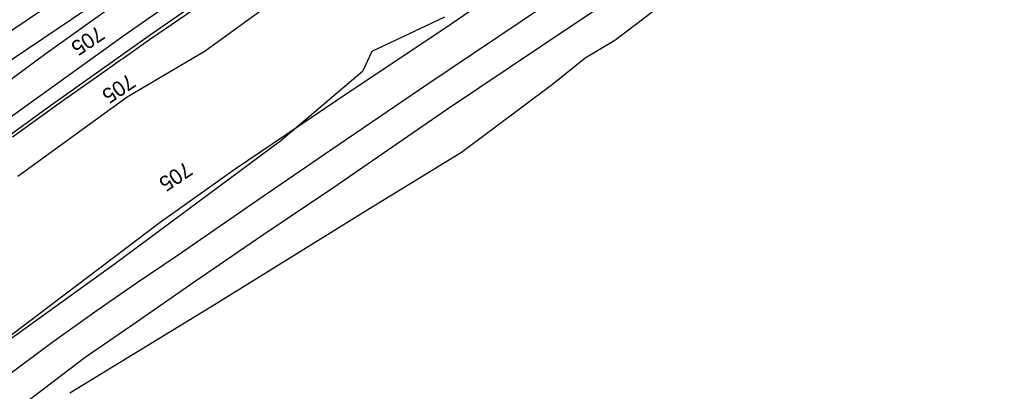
# Model space of a CAD drawing. Extents: x 1901471 to 1963503, y 756461 to 799997.
# Drawn here: x 1912983 to 1913505, y 762217 to 762413 of the extents above; entities that cross this region are included whole.
import ezdxf

# ---------------------------------------------------------------- set-up
doc = ezdxf.new("R2010")
doc.units = 0
for name, color, linetype in [('RD_DTM_BkLn1', 7, 'Continuous'), ('RD_EX_Fence_Other', 7, 'Continuous'), ('RD_EX_Road', 7, 'Continuous'), ('RD_EX_VEG', 7, 'Continuous'), ('RD_HC_Cl', 7, 'Continuous'), ('RD_HC_TX_Sta50', 7, 'Continuous')]:
    doc.layers.add(name, color=color, linetype=linetype)

msp = doc.modelspace()

# ---------------------------------------------------------------- linework, layer by layer
at = {"layer": 'RD_DTM_BkLn1'}
msp.add_lwpolyline([(1912979.4969465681, 762351.1621275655), (1912987.6589494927, 762356.9334477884), (1912987.8265054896, 762357.0519259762), (1912995.9306917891, 762362.9094845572), (1913004.0348780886, 762368.7670431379), (1913007.028080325, 762370.9304753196), (1913015.2423514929, 762376.6325534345), (1913020.062154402, 762379.9783028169), (1913028.2179814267, 762385.7639288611), (1913036.373808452, 762391.5495549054), (1913037.5192204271, 762392.3620936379), (1913045.6917357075, 762398.1247516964), (1913051.63551127, 762402.3158660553), (1913059.854179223, 762408.01020824), (1913066.4409205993, 762412.5738625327), (1913074.739521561, 762418.1534052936)], dxfattribs=at)
at = {"layer": 'RD_EX_Fence_Other'}
msp.add_lwpolyline([(1912667.5000000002, 761887.4300000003), (1912688.7900000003, 761925.8900000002), (1912721.4800000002, 761980.6200000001), (1912763.5000000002, 762038.58), (1912800.5900000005, 762082.32), (1912831.6300000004, 762117.8900000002), (1912847.2800000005, 762135.6800000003), (1912879.5600000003, 762168.0200000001), (1912904.9700000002, 762190.9600000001), (1913057.2900000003, 762306.1300000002), (1913096.6200000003, 762334.2200000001), (1913156.6200000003, 762374.7600000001), (1913206.9900000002, 762408.3700000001), (1913295.2800000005, 762468.9700000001), (1913371.6300000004, 762520.1800000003), (1913441.4500000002, 762567.1400000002), (1913480.6800000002, 762594.4000000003), (1913520.7900000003, 762621.3)], dxfattribs=at)
at = {"layer": 'RD_EX_Road'}
for points in [[(1913587.6100000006, 762789.6500000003), (1913498.2000000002, 762726.83), (1913412.8100000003, 762666.6100000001), (1913337.5200000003, 762613.3700000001), (1913299.64, 762586.8800000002), (1913247.5400000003, 762550.4800000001), (1913143.1100000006, 762477.56), (1913037.5200000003, 762403.9500000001), (1912980.0700000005, 762362.55), (1912916.5700000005, 762314.5200000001), (1912861.9100000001, 762270.0900000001), (1912825.8600000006, 762236.9500000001), (1912785.39, 762195.7800000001), (1912744.9200000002, 762149.9600000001), (1912704.9400000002, 762100.4300000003), (1912698.3300000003, 762091.2200000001), (1912671.2500000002, 762053.3600000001), (1912648.9000000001, 762018.4900000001), (1912625.4400000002, 761979.2100000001), (1912601.5100000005, 761937.58), (1912575.2200000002, 761889.8), (1912536.1800000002, 761819.2000000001), (1912511.1500000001, 761773.7000000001)], [(1913524.5200000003, 762735.8900000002), (1913475.7200000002, 762701.56), (1913384.4000000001, 762636.9900000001), (1913299.4100000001, 762575.83), (1913192.8800000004, 762502.2100000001), (1913051.4700000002, 762404.1800000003), (1912997.7400000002, 762366.1500000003), (1912940.2900000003, 762324.5200000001), (1912881.6800000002, 762279.05), (1912846.3300000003, 762248.1100000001), (1912802.3700000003, 762204.7300000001), (1912747.7100000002, 762143.9100000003), (1912713.7000000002, 762100.1900000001), (1912698.7500000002, 762080.0100000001), (1912668.3600000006, 762037.2800000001), (1912632.9800000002, 761980.3600000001), (1912596.8600000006, 761915.9600000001), (1912554.0100000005, 761839.1000000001), (1912516.14, 761769.9700000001)], [(1912950.2000000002, 762203.3400000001), (1912976.1600000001, 762224.9700000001), (1913000.2000000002, 762242.83), (1913024.0900000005, 762259.9300000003), (1913044.1500000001, 762273.8), (1913066.6700000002, 762289.0400000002), (1913108.0100000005, 762317.6800000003), (1913146.8800000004, 762344.32), (1913197.4200000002, 762378.5900000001), (1913259.3600000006, 762420.1400000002), (1913291.6300000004, 762442.2500000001), (1913300.0100000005, 762447.81), (1913380.5900000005, 762502.6600000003), (1913460.1100000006, 762555.9100000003), (1913505.2800000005, 762587.05)], [(1913519.0800000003, 762575.2800000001), (1913449.6000000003, 762528.31), (1913360.0400000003, 762468.0000000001), (1913300.0100000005, 762427.2100000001), (1913257.1600000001, 762398.5000000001), (1913208.2700000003, 762365.6100000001), (1913147.9800000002, 762324.07), (1913111.7200000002, 762299.7600000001), (1913075.1800000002, 762274.6900000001), (1913044.5600000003, 762253.4000000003), (1913017.7800000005, 762234.9300000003), (1912986.1900000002, 762210.9000000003)], [(1912576.7900000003, 761925.9600000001), (1912600.5400000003, 761968.3900000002), (1912620.1900000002, 762002.5100000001), (1912639.1900000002, 762033.7100000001), (1912661.8700000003, 762068.2600000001), (1912684.5400000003, 762100.2200000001), (1912720.7300000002, 762146.82), (1912752.8300000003, 762184.5000000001), (1912797.7200000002, 762232.5300000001), (1912852.6100000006, 762283.4700000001), (1912878.6600000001, 762305.1000000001), (1912938.6700000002, 762351.7300000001), (1912996.5800000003, 762394.6400000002), (1913061.2400000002, 762440.9300000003), (1913058.4500000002, 762445.2300000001), (1912971.6900000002, 762386.7300000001), (1912859.1200000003, 762310.7900000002), (1912776.5500000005, 762255.55), (1912732.5900000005, 762226.0200000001), (1912650.9500000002, 762170.4300000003), (1912603.9700000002, 762139.0300000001), (1912546.3400000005, 762100.1100000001)]]:
    msp.add_lwpolyline(points, dxfattribs=at)
at = {"layer": 'RD_EX_VEG'}
for points in [[(1913009.7800000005, 762216.3600000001), (1913086.7100000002, 762263.5100000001), (1913166.4700000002, 762312.9600000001), (1913215.7400000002, 762343.0900000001), (1913263.6000000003, 762378.9000000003), (1913280.6200000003, 762392.7200000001), (1913296.2200000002, 762401.9400000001), (1913368.1000000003, 762456.6100000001), (1913431.3100000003, 762498.8500000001), (1913469.8300000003, 762527.2700000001), (1913498.2500000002, 762551.0400000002), (1913522.6900000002, 762563.2600000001)], [(1912982.39, 762330.3600000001), (1913039.8200000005, 762372.1900000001), (1913080.9400000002, 762396.3), (1913139.4400000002, 762439.0100000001)], [(1913206.7900000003, 762414.0200000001), (1913168.5000000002, 762395.9400000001), (1913163.5400000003, 762385.4800000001), (1913120.6500000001, 762348.9700000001), (1913033.7900000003, 762284.4500000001), (1912966.4400000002, 762236.06)]]:
    msp.add_lwpolyline(points, dxfattribs=at)
at = {"layer": 'RD_HC_Cl'}
msp.add_line((1916195.7651138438, 764578.0862627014), (1911854.4508108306, 761647.9472216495), dxfattribs=at)

# ---------------------------------------------------------------- texts
at = {"layer": 'RD_HC_TX_Sta50'}
for rotation, p in [(214.00882459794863, (1913024.3694472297, 762409.9289395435)), (214.00852866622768, (1913040.6380679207, 762384.7289041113)), (214.01710034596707, (1913070.5857762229, 762338.471044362))]:
    msp.add_text('705', height=8.000000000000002, rotation=rotation, dxfattribs=at).set_placement(p)

doc.saveas('drawing.dxf')
